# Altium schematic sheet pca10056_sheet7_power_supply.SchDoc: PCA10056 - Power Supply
size A3; Organization: Nordic Semiconductor; DocumentNumber: 7; SheetNumber: 7; SheetTotal: 7; CompanyName: Nordic Semiconductor
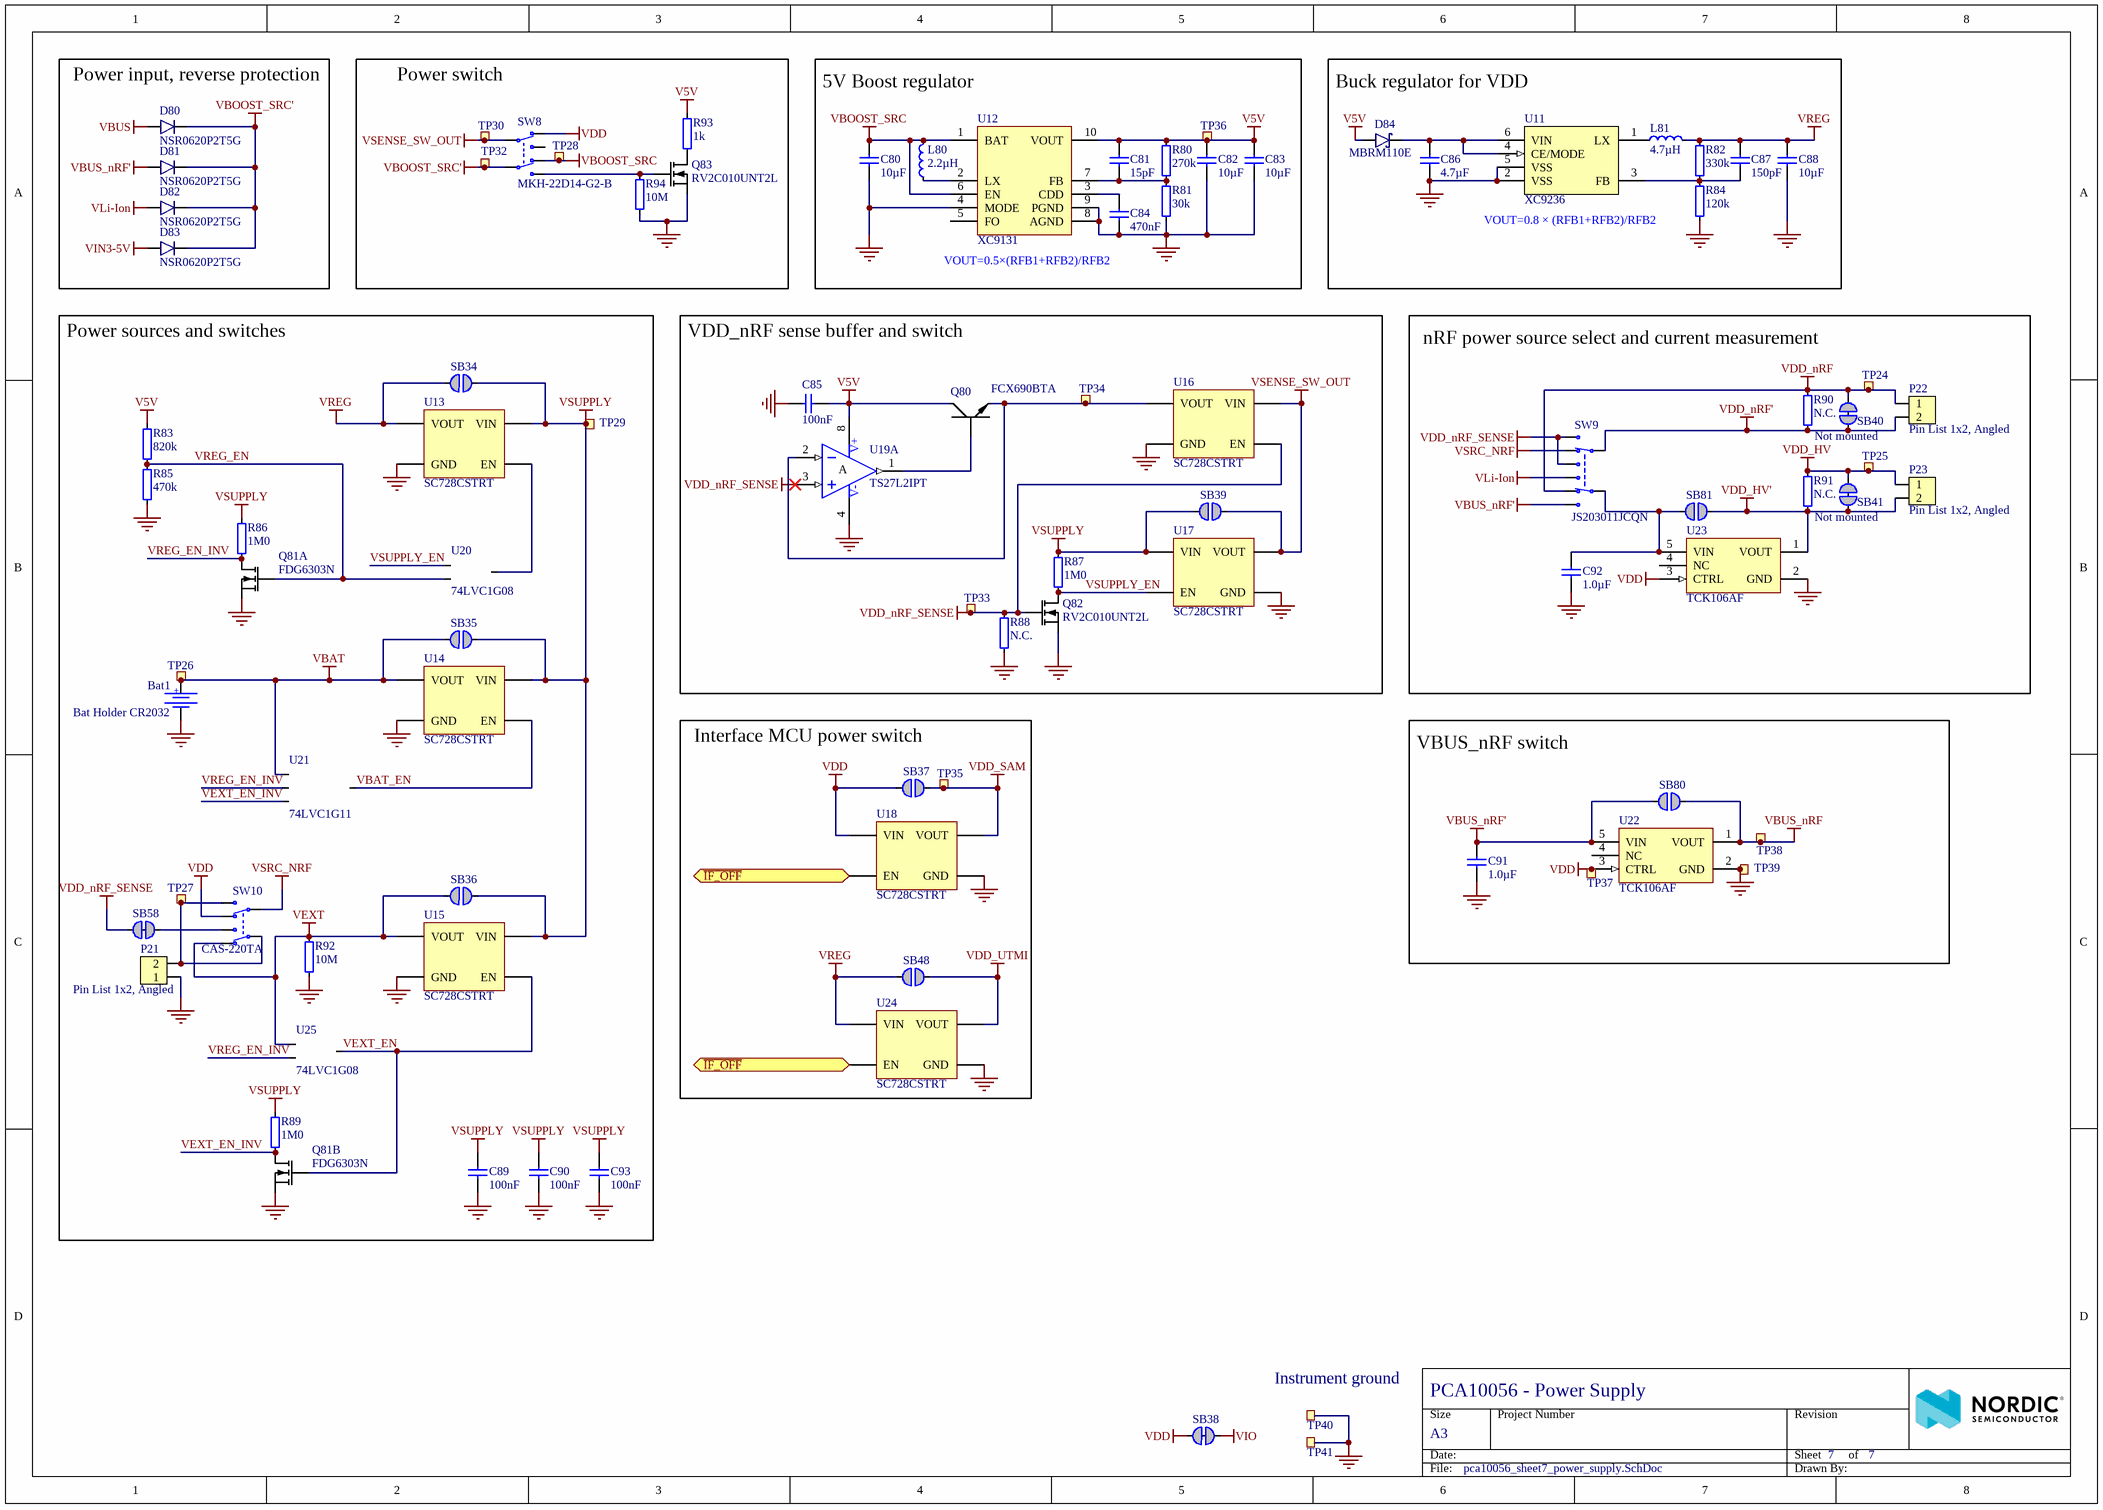
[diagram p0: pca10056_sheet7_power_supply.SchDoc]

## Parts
Bat1  Bat Holder CR2032  [CR2032_HOLDER_SMD]
C80  10µF  [CAPC1608X06L]
C81  15pF  [CAPC1005X04L]
C82  10µF  [CAPC1608X06L]
C83  10µF  [CAPC1608X06L]
C84  470nF  [CAPC1005X04L]
C85  100nF  [CAPC1005X04L]
C86  4.7µF  [CAPC2012X11L]
C87  150pF  [CAPC1005X04L]
C88  10µF  [CAPC1608X06L]
C89  100nF  [CAPC1005X04L]
C90  100nF  [CAPC1005X04L]
C91  1.0µF  [CAPC1608X06L]
C92  1.0µF  [CAPC1608X06L]
C93  100nF  [CAPC1005X04L]
D80  NSR0620P2T5G  [SODFL100X40-2N]
D81  NSR0620P2T5G  [SODFL100X40-2N]
D82  NSR0620P2T5G  [SODFL100X40-2N]
D83  NSR0620P2T5G  [SODFL100X40-2N]
D84  MBRM110E  [DO-216AA]
L80  2.2µH  [TY-NR3015]
L81  4.7µH  [TY-NR3015]
P21  Pin List 1x2, Angled  [LIST_ANG_1x2-SMD-2.54MM]
P22  Pin List 1x2, Angled  [LIST_ANG_1x2-SMD-2.54MM]
P23  Pin List 1x2, Angled  [LIST_ANG_1x2-SMD-2.54MM]
Q80  FCX690BTA  [SOT89-150P409X160-3N]
Q81  FDG6303N  [SOT65P210X100-6N]  (parts A,B of 2)
Q82  RV2C010UNT2L  [DFN65P100X40-3L]
Q83  RV2C010UNT2L  [DFN65P100X40-3L]
R80  270k  [RESC1005X04L]
R81  30k  [RESC1005X04L]
R82  330k  [RESC1005X04L]
R83  820k  [RESC1005X04L]
R84  120k  [RESC1005X04L]
R85  470k  [RESC1005X04L]
R86  1M0  [RESC1005X04L]
R87  1M0  [RESC1005X04L]
R88  N.C.  [RESC1005X04L]
R89  1M0  [RESC1005X04L]
R90  N.C.  Assembly: Not mounted  [RESC1005X04L]
R91  N.C.  Assembly: Not mounted  [RESC1005X04L]
R92  10M  [RESC1005X04L]
R93  1k  [RESC1005X04L]
R94  10M  [RESC1005X04L]
SB34  Solderbridge  [Solderbridge]  (value not drawn)  (no BOM)
SB35  Solderbridge  [Solderbridge]  (value not drawn)  (no BOM)
SB36  Solderbridge  [Solderbridge]  (value not drawn)  (no BOM)
SB37  Solderbridge  [Solderbridge]  (value not drawn)  (no BOM)
SB38  Solderbridge  [Solderbridge_Shorted]  (value not drawn)  (net tie, no BOM)
SB39  Solderbridge  [Solderbridge]  (value not drawn)  (no BOM)
SB40  Solderbridge  [Solderbridge_Shorted]  (value not drawn)  (net tie, no BOM)
SB41  Solderbridge  [Solderbridge_Shorted]  (value not drawn)  (net tie, no BOM)
SB48  Solderbridge  [Solderbridge]  (value not drawn)  (no BOM)
SB58  Solderbridge  [Solderbridge_Shorted]  (value not drawn)  (net tie, no BOM)
SB80  Solderbridge  [Solderbridge]  (value not drawn)  (no BOM)
SB81  Solderbridge  [Solderbridge]  (value not drawn)  (no BOM)
SW8  MKH-22D14-G2-B  [MKH-22D14-G2-B]
SW9  JS203011JCQN  [Switch-Slide-J-Lead-DP3T-13x3.5mm]
SW10  CAS-220TA  [CAS-220TA]
TP24  Ø1.0mm,SMD  [TP_SMD_Ø1.0mm]  (value not drawn)  (no BOM)
TP25  Ø1.0mm,SMD  [TP_SMD_Ø1.0mm]  (value not drawn)  (no BOM)
TP26  Ø1.0mm,SMD  [TP_SMD_Ø1.0mm]  (value not drawn)  (no BOM)
TP27  Ø1.0mm,SMD  [TP_SMD_Ø1.0mm]  (value not drawn)  (no BOM)
TP28  Ø1.0mm,SMD  [TP_SMD_Ø1.0mm]  (value not drawn)  (no BOM)
TP29  Ø1.0mm,SMD  [TP_SMD_Ø1.0mm]  (value not drawn)  (no BOM)
TP30  Ø1.0mm,SMD  [TP_SMD_Ø1.0mm]  (value not drawn)  (no BOM)
TP32  Ø1.0mm,SMD  [TP_SMD_Ø1.0mm]  (value not drawn)  (no BOM)
TP33  Ø1.0mm,SMD  [TP_SMD_Ø1.0mm]  (value not drawn)  (no BOM)
TP34  Ø1.0mm,SMD  [TP_SMD_Ø1.0mm]  (value not drawn)  (no BOM)
TP35  Ø1.0mm,SMD  [TP_SMD_Ø1.0mm]  (value not drawn)  (no BOM)
TP36  Ø1.0mm,SMD  [TP_SMD_Ø1.0mm]  (value not drawn)  (no BOM)
TP37  Ø1.0mm,SMD  [TP_SMD_Ø1.0mm]  (value not drawn)  (no BOM)
TP38  Ø1.0mm,SMD  [TP_SMD_Ø1.0mm]  (value not drawn)  (no BOM)
TP39  Ø1.0mm,SMD  [TP_SMD_Ø1.0mm]  (value not drawn)  (no BOM)
TP40  TP  [TESTPAD-TH]  (value not drawn)  (no BOM)
TP41  TP  [TESTPAD-TH]  (value not drawn)  (no BOM)
U11  XC9236  [USP-6C]
U12  XC9131  [10-USPB (2.9x2.6)]
U13  SC728CSTRT  [BGA4C40P2X2_76X76X62]
U14  SC728CSTRT  [BGA4C40P2X2_76X76X62]
U15  SC728CSTRT  [BGA4C40P2X2_76X76X62]
U16  SC728CSTRT  [BGA4C40P2X2_76X76X62]
U17  SC728CSTRT  [BGA4C40P2X2_76X76X62]
U18  SC728CSTRT  [BGA4C40P2X2_76X76X62]
U19  TS27L2IPT  [TSOP65P640X120-8N]  (part A of 2)
U20  74LVC1G08  [SOT65P210X100-5N]
U21  74LVC1G11  [SOT65P210X100-6N]
U22  TCK106AF  [SOT95P280X140-5N]
U23  TCK106AF  [SOT95P280X140-5N]
U24  SC728CSTRT  [BGA4C40P2X2_76X76X62]
U25  74LVC1G08  [SOT65P210X100-5N]

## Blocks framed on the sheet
Power input, reverse protection: D80-D83
Power switch: Q83 R93 R94 SW8 TP28 TP30 TP32
5V Boost regulator: C80-C84 L80 R80 R81 TP36 U12
Buck regulator for VDD: C86-C88 D84 L81 R82 R84 U11
Power sources and switches: Bat1 C89 C90 C93 P21 Q81 R83 R85 R86 R89 R92 SB34-SB36 SB58 SW10 TP26 TP27 TP29 U13-U15 U20 U21 U25
VDD_nRF sense buffer and switch: C85 Q80 Q82 R87 R88 SB39 TP33 TP34 U16 U17 U19
nRF power source select and current measurement: C92 P22 P23 R90 R91 SB40 SB41 SB81 SW9 TP24 TP25 U23
Interface MCU power switch: SB37 SB48 TP35 U18 U24
VBUS_nRF switch: C91 SB80 TP37-TP39 U22

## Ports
~{IF_OFF} (bidir)

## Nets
GND: Bat1.2 C80.1 C82.1 C83.1 C84.1 C85.1 C86.1 C88.1 C89.1 C90.1 C91.1 C92.1 C93.1 P21.1 Q81.1(S1) Q81.4(S2) Q82.2(S) Q83.2(S) R81.1 R84.1 R85.2 R88.2 R92.2 R94.2 TP39.1 TP40.1 TP41.1 U11.2(VSS) U11.5(VSS) U11.7(VSS) U12.4(MODE) U12.8(AGND) U12.9(PGND) U12.11(GND) U13.B1(GND) U14.B1(GND) U15.B1(GND) U16.B1(GND) U17.B1(GND) U18.B1(GND) U19.4(V-) U20.3(GND) U21.2(GND) U22.2(GND) U23.2(GND) U24.B1(GND) U25.3(GND)
V5V: C81.2 C82.2 C83.2 C85.2 D84.1(A) Q80.2(C) R80.2 R83.1 R93.1 TP36.1 U12.10(VOUT) U19.8(V+)
VBAT: Bat1.1 SB35.2 TP26.1 U14.A1(VOUT) U21.1(A)
VBOOST_SRC: C80.2 L80.2 SW8.6(N.C-2) TP28.1 U12.1(BAT) U12.6(EN)
VBOOST_SRC': D80.1(C) D81.1(C) D82.1(C) D83.1(C) SW8.5(COM-2) TP32.1
VBUS: D80.2(A)
VBUS_nRF: SB80.1 TP38.1 U22.1(VOUT)
VBUS_nRF': C91.2 D81.2(A) SB80.2 SW9.8(N.O) U22.5(VIN)
VDD: SB37.2 SB38.2 SW8.3(N.C-1) SW10.6(N.C-2) TP37.1 U18.A2(VIN) U22.3(CTRL) U23.3(CTRL)
VDD_HV: P23.1 R91.2 SB41.1 TP25.1
VDD_HV': P23.2 R91.1 SB41.2 SB81.1 U23.1(VOUT)
VDD_nRF: P22.1 R90.2 SB40.1 SW9.6(N.C) TP24.1
VDD_nRF': P22.2 R90.1 SB40.2 SW9.3(COM)
VDD_nRF_SENSE: Q82.1(G) R88.1 SB58.1 SW9.1(N.O) SW9.4(N.O) TP33.1 U16.B2(EN) U19.3(IN1+)
VDD_SAM: SB37.1 TP35.1 U18.A1(VOUT)
VDD_UTMI: SB48.1 U24.A1(VOUT)
VEXT: R92.1 SB36.2 SW10.3(N.C-1) U15.A1(VOUT) U25.1(A)
VIN3-5V: D83.2(A)
VIO: SB38.1
VLi-Ion: D82.2(A) SW9.5(N.O)
VREG: C87.2 C88.2 L81.2 R82.2 SB34.2 SB48.2 U13.A1(VOUT) U24.A2(VIN)
VSENSE_SW_OUT: SB39.1 SW8.2(COM-1) TP30.1 U16.A2(VIN) U17.A1(VOUT)
VSRC_NRF: SW9.2(N.C) SW10.5(COM-2)
VSUPPLY: C89.2 C90.2 C93.2 R86.1 R87.1 R89.1 SB34.1 SB35.1 SB36.1 SB39.2 TP29.1 U13.A2(VIN) U14.A2(VIN) U15.A2(VIN) U17.A2(VIN) U20.5(VCC) U21.5(VCC) U25.5(VCC)
~{IF_OFF}: U18.B2(EN) U24.B2(EN) ; port ~{IF_OFF}
VBAT_EN: U14.B2(EN) U21.4(Y)
VEXT_EN: Q81.5(G2) U15.B2(EN) U25.4(Y)
VEXT_EN_INV: Q81.3(D2) R89.2 U21.6(C)
VREG_EN: Q81.2(G1) R83.2 R85.1 U20.2(B)
VREG_EN_INV: Q81.6(D1) R86.2 U21.3(B) U25.2(B)
VSUPPLY_EN: Q82.3(D) R87.2 U17.B2(EN) U20.1(A)
NetC81_1: C81.1 R80.1 R81.2 U12.7(FB)
NetC84_2: C84.2 U12.3(CDD)
NetC86_2: C86.2 D84.3(C) U11.4(CE/MODE) U11.6(VIN)
NetC87_1: C87.1 R82.1 R84.2 U11.3(FB)
NetC92_2: C92.2 SB81.2 SW9.7(COM) U23.5(VIN)
NetL80_1: L80.1 U12.2(LX)
NetL81_1: L81.1 U11.1(LX)
NetP21_2: P21.2 SW10.2(COM-1) SW10.4(N.O-2) TP27.1
NetQ80_1: Q80.1(B) U19.1(OUT1)
NetQ80_3: Q80.3(E) TP34.1 U16.A1(VOUT) U19.2(IN1-)
NetQ83_1: Q83.1(G) R94.1 SW8.4(N.O-2)
NetQ83_3: Q83.3(D) R93.2
NetSB58_2: SB58.2 SW10.1(N.O-1)
NetU13_B2: U13.B2(EN) U20.4(Y)

Not connected (* = marked no-connect by the designer): SW8 1(N.O-1); U12 5(FO); U22 4(NC); U23 4(NC)

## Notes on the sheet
- VOUT=0.8 × (RFB1+RFB2)/RFB2
- VOUT=0.5×(RFB1+RFB2)/RFB2
- (near TP40) Instrument ground

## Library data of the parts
Bat1 = Bat Holder CR2032 SMD: Manufacturer: Comfortable; Manufacturer Part Number: BC-2001; 2nd source part number: 165-0693; Artikkelnr Noca: 55089011; Artikkelnr Simpro: N.A.
C80 C82 C83 C88 = C0603-10µF-25V: Capacitor, 0603, 25V, X5R; Artikkelnr Noca: 20039436; Artikkelnr Simpro: N.A.
C81 = C0402-15p: Capacitor, NP0, ±5%; Part number IPS: 00000002401; Note: 50V; Artikkelnr Noca: 20029141; Artikkelnr Simpro: N.A.
C84 = C0402-470n: Capacitor, X5R, ±10%; Note: 6.3V; Artikkelnr Noca: 20039350; Artikkelnr Simpro: N.A.
C85 C89 C90 C93 = C0402-100n: Capacitor, X7R, ±10%; Part number IPS: 00000005296; Note: 16V; Artikkelnr Noca: 20039200; Artikkelnr Simpro: N.A.
C86 = C0805-4µ7: Capacitor, X5R, ±10%; Note: 16V; Artikkelnr Noca: 20039266; Artikkelnr Simpro: N.A.
C87 = C0402-150p: Capacitor, NP0, ±5%; Part number IPS: 00000007972; Note: 50V; Artikkelnr Noca: 20029111; Artikkelnr Simpro: N.A.
C91 C92 = C0603-1µ0: Capacitor, X7R, ±10%; Part number IPS: 00000000616; Note: 16V; Artikkelnr Noca: 20039335; Artikkelnr Simpro: N.A.
D80-D83 = NSR0620P2T5G: 20V schottky barrier diode, Vf 350 mV @ 100 mA, Ir 2.0 µA @ 10 V, If 500 mA; Manufacturer: ON Semiconductor; Artikkelnr Noca: 10029169; Artikkelnr Simpro: N.A.
D84 = MBRM110E: Diode Schottky Vf=0.455V @ 100mA, Vr=10V, If=1000mA, Ir=1µA @ 10V; Manufacturer: ON Semiconductor; Manufacturer Part Number: MBRM110ET1G; 2nd source part number: 236-9429; Artikkelnr Noca: 10029172; Artikkelnr Simpro: N.A.
L80 = NR3015-2µ2-1.5A-72mOhm: Ferrite Inductor, Shielded, 1,5A, 72mOhm; Manufacturer: Taiyo Yuden; Manufacturer Part Number: NR3015T2R2M; 2nd source part number: 188-5853; Artikkelnr Noca: 33029487; Artikkelnr Simpro: N.A.
L81 = NR3015-4µ7-1.04A-144mOhm: Ferrite Inductor, Shielded, 1,04A, 144mOhm; Manufacturer: Taiyo Yuden; Manufacturer Part Number: NR3015T4R7M; 2nd source part number: 963-NR3015T4R7M; Artikkelnr Noca: 33029551; Artikkelnr Simpro: N.A.
P21-P23 = Pin List Ang 1x2 SMD, 2.54mm: Pin List 1x2, 2.54mm (100mil), Right Angled, SMD; Manufacturer: W-CON; Manufacturer Part Number: 1125B-1102S0Z135R2; 2nd source part number: TSM-102-01-L-SH-A; Artikkelnr Noca: 55010023; Artikkelnr Simpro: N.A.
Q80 = FCX690BTA: 45V NPN high gain power transistor; Manufacturer: Diodes Incorporated; Artikkelnr Noca: 35010019; Artikkelnr Simpro: N.A.
Q81 = FDG6303N: Fairchild, FDG6303N, Dual N-Channel Digital FET; 2nd source part number: FDG6303NCT-ND; Artikkelnr Noca: 35029086; Artikkelnr Simpro: N.A.
Q82 Q83 = RV2C010UNT2L: N-Channel MOSFET, 20V, 1A, 470mOhm, 400mW; Manufacturer: Rohm Semiconductor; 2nd source part number: 755-RV2C010UNT2L; Artikkelnr Noca: 35010020; Artikkelnr Simpro: N.A.
R80 = R0402-270k: Resistor, ±1%, 0.063W; Note: Chip Res 1%; Artikkelnr Noca: 27049131; Artikkelnr Simpro: N.A.; Value Ohm: 270000
R81 = R0402-30k: Resistor, ±1%, 0.063W; Note: Chip Res 1%; Artikkelnr Noca: 27049108; Artikkelnr Simpro: N.A.; Value Ohm: 30000
R82 = R0402-330k: Resistor, ±1%, 0.063W; Note: Chip Res 1%; Artikkelnr Noca: 27049133; Artikkelnr Simpro: N.A.; Value Ohm: 330000
R83 = R0402-820k: Resistor, ±1%, 0.063W; Note: Chip Res 1%; Artikkelnr Noca: 27049143; Artikkelnr Simpro: N.A.; Value Ohm: 820000
R84 = R0402-120k: Resistor, ±1%, 0.063W; Note: Chip Res 1%; Artikkelnr Noca: 27049123; Artikkelnr Simpro: N.A.; Value Ohm: 120000
R85 = R0402-470k: Resistor, ±1%, 0.063W; Note: Chip Res 1%; Artikkelnr Noca: 27049137; Artikkelnr Simpro: N.A.; Value Ohm: 470000
R86 R87 R89 = R0402-1M0: Resistor, ±1%, 0.063W; Part number IPS: 00000006807; Note: Chip Res 1%; Artikkelnr Noca: 27049145; Artikkelnr Simpro: N.A.; Value Ohm: 1000000
R88 = R0402-N.C.: Not mounted; Note: Chip Res; Artikkelnr Noca: N.A.; Assembly: Not mounted
R90 R91 = R0402-N.C.: Not mounted; Note: Chip Res; Artikkelnr Noca: N.A.
R92 R94 = R0402-10M: Resistor, ±1%, 0.063W; Note: Chip Res 1%; Artikkelnr Noca: 27049169; Artikkelnr Simpro: N.A.; Value Ohm: 10000000
R93 = R0402-1k0: Resistor, ±1%, 0.063W; Part number IPS: 00000002218; Note: Chip Res 1%; Artikkelnr Noca: 27049073; Artikkelnr Simpro: N.A.; Value Ohm: 1000
SB34-SB37 SB39 SB48 SB80 SB81 = Solderbridge: Artikkelnr Noca: N.A.
SB38 SB40 SB41 SB58 = Solderbridge Shorted: Shorted Solderbridge; Artikkelnr Noca: N.A.
SW8 = MKH-22D14-G2-B: Slide Switch DPDT; Manufacturer: Dailywell; Artikkelnr Noca: 50019112; Artikkelnr Simpro: N.A.
SW9 = JS203011JCQN: Slide Switch DP3T 300mA 6V; Manufacturer: C&K Components; Artikkelnr Noca: 50019111; Artikkelnr Simpro: N.A.
SW10 = CAS-220TA: Slide Switch DPDT J Hook; Manufacturer: Copal Electronics Inc; Artikkelnr Noca: 50019042; Artikkelnr Simpro: N.A.
TP24-TP30 TP32-TP39 = TP_SMD_Ø1.0MM: 1.0mm circular SMD testpad; Manufacturer: Nordic Semiconductor; Artikkelnr Noca: N.A.
TP40 TP41 = Testpoint TH: Testpoint, through hole; Artikkelnr Noca: N.A.
U11 = XC9236D08CER-G: 600mA Driver Transistor Built-In, Synchronous Step-Down DC/DC Converters; Manufacturer: Torex Semiconductor; 2nd source part number: XC9236D08CER-G-ND; Artikkelnr Noca: 17030085; Artikkelnr Simpro: N.A.
U12 = XC9131H05CDR-G: 1A Driver Transistor Built-In, Multi Functional Step-Up DC/DC Converter; Manufacturer: Torex Semiconductor; Artikkelnr Noca: 17030086; Artikkelnr Simpro: N.A.
U13-U18 U24 = SC728CSTRT: Semtech, 2A Low Vin, Very Low Ron, Load Switch, 4DSBGA; Manufacturer: Semtech Corporation; 2nd source part number: 947-SC728CSTRT; Artikkelnr Noca: 15070081; Artikkelnr Simpro: N.A.
U19 = TS27L2IPT: Precision very low power CMOS dual operational amplifier; Manufacturer: STMicroelectronics; Artikkelnr Noca: 17010019; Artikkelnr Simpro: N.A.
U20 U25 = 74LVC1G08GW: Single 2-Input AND Gate; Manufacturer: NXP Semiconductors; 2nd source part number: 242-8299; Artikkelnr Noca: 15049058; Artikkelnr Simpro: N.A.
U21 = 74LVC1G11GW: Single 3-input AND gate; Manufacturer: NXP Semiconductors; 2nd source part number: 243-8826; Artikkelnr Noca: 15079348; Artikkelnr Simpro: N.A.
U22 U23 = TCK106AF,LF: 1.0 A Load Switch IC with Slew Rate Control Driver in Small Package; Manufacturer: Toshiba; Part number IPS: 00000007823; Artikkelnr Noca: 15070086; Artikkelnr Simpro: N.A.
